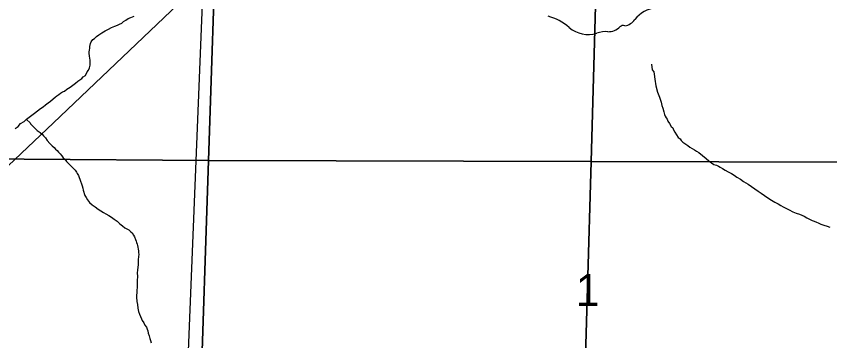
# Model space of a CAD drawing. Extents: x 2010165 to 2382125, y 1060529 to 1407316.
# Drawn here: x 2158400 to 2164031, y 1243143 to 1245392 of the extents above; entities that cross this region are included whole.
import ezdxf

# ---------------------------------------------------------------- set-up
doc = ezdxf.new("R2010")
doc.units = 0
for name, color, linetype in [('GM_X_City_Street', 7, 'Continuous'), ('GM_X_Minor_River', 7, 'Continuous'), ('GM_X_Rail_Line', 7, 'Continuous'), ('GM_X_Section', 7, 'Continuous'), ('GM_X_Section_Text', 7, 'Continuous'), ('GM_X_State_Shield', 7, 'Continuous')]:
    doc.layers.add(name, color=color, linetype=linetype)

msp = doc.modelspace()

# ---------------------------------------------------------------- linework, layer by layer
at = {"layer": 'GM_X_City_Street'}
msp.add_lwpolyline([(2159318.5, 1235161.2), (2159514.5, 1240755.7), (2159578.1, 1242229.6), (2159584.2, 1242899.4), (2159715.4, 1246110.5)], dxfattribs=at)
at = {"layer": 'GM_X_Minor_River'}
for points in [[(2158954.7, 1245251.2), (2158972.5, 1245263.5), (2158992.3, 1245278), (2159016.2, 1245290.5), (2159038, 1245302.9), (2159059.9, 1245313.4), (2159081.8, 1245323.8), (2159099.7, 1245330.2), (2159113.6, 1245336.5), (2159129.5, 1245344.8), (2159141.4, 1245355.1), (2159157.2, 1245365.4), (2159175.1, 1245375.8), (2159193, 1245384.1), (2159205, 1245388.4), (2159214.9, 1245392.6)], [(2158392.6, 1244614.3), (2158412.4, 1244628.7), (2158430, 1244649.1), (2158453.9, 1244663.6), (2158471.6, 1244678), (2158489.4, 1244692.4), (2158507.2, 1244706.8), (2158527, 1244721.2), (2158546.8, 1244737.6), (2158568.6, 1244752.1), (2158586.4, 1244764.5), (2158602.2, 1244778.8), (2158620.1, 1244791.2), (2158635.9, 1244803.6), (2158655.6, 1244820), (2158669.5, 1244830.3), (2158681.3, 1244840.5), (2158695.2, 1244850.8), (2158707.1, 1244859.1), (2158721, 1244867.4), (2158732.9, 1244873.6), (2158750.7, 1244886), (2158760.6, 1244894.2), (2158772.5, 1244900.5), (2158790.3, 1244914.9), (2158800.3, 1244921.1), (2158810.1, 1244929.3), (2158826, 1244941.6), (2158839.8, 1244951.9), (2158853.7, 1244960.2), (2158863.5, 1244972.5), (2158879.4, 1244980.8), (2158891, 1245007.1), (2158898.8, 1245019.3), (2158906.5, 1245033.5), (2158912.2, 1245053.7), (2158912, 1245065.7), (2158911.7, 1245077.8), (2158911.5, 1245087.8), (2158909.3, 1245101.8), (2158907, 1245115.8), (2158904.6, 1245135.8), (2158904.4, 1245145.8), (2158906.3, 1245155.9), (2158908, 1245170), (2158909.8, 1245182.1), (2158913.4, 1245204.2), (2158917.2, 1245214.3), (2158929, 1245230.6), (2158940.9, 1245238.9), (2158954.7, 1245251.2)], [(2162797.2, 1245059.7), (2162801.9, 1245021.6), (2162812.2, 1245007.8), (2162816.5, 1244991.8), (2162821.2, 1244955.8), (2162828.1, 1244909.8), (2162838.9, 1244865.8), (2162851.6, 1244831.9), (2162864.3, 1244796.1), (2162868.7, 1244774.1), (2162875.1, 1244756.1), (2162881.6, 1244730.2), (2162887.9, 1244712.2), (2162892.1, 1244700.3), (2162898.4, 1244688.3), (2162904.6, 1244678.4), (2162910.9, 1244664.5), (2162921.2, 1244648.6), (2162933.6, 1244628.8), (2162943.8, 1244619), (2162950.1, 1244605), (2162958.4, 1244589.1), (2162970.8, 1244569.3), (2162981.2, 1244551.4), (2162995.4, 1244541.7), (2163001.6, 1244531.8), (2163013.9, 1244520), (2163028.1, 1244510.2), (2163048.4, 1244496.5), (2163062.7, 1244484.8), (2163078.9, 1244475.1), (2163095.1, 1244467.3), (2163109.4, 1244457.6), (2163123.6, 1244447.8), (2163174.5, 1244406.6), (2163192.9, 1244390.9), (2163213.2, 1244377.3), (2163229.5, 1244365.6), (2163247.6, 1244359.9), (2163259.8, 1244354.1), (2163272, 1244346.3), (2163288.2, 1244336.6), (2163306.5, 1244324.9), (2163328.8, 1244313.2), (2163351.1, 1244301.6), (2163369.3, 1244289.9), (2163387.7, 1244276.2), (2163412, 1244262.7), (2163434.3, 1244247), (2163466.8, 1244227.6), (2163489.2, 1244212), (2163511.6, 1244196.3), (2163535.9, 1244180.8), (2163556.3, 1244165.1), (2163578.6, 1244149.5), (2163603, 1244133.9), (2163627.4, 1244118.3), (2163651.7, 1244104.7), (2163674, 1244091.1), (2163692.3, 1244081.4), (2163708.5, 1244071.7), (2163730.8, 1244060), (2163751.1, 1244050.4), (2163775.4, 1244036.8), (2163797.6, 1244027.2), (2163821.9, 1244019.6), (2163838, 1244013.9), (2163854.2, 1244006.2), (2163872.5, 1243994.5), (2163890.7, 1243984.8), (2163908.9, 1243977.1), (2163923.1, 1243971.4), (2163939.3, 1243965.7), (2163951.4, 1243959.9), (2163969.6, 1243952.2), (2163989.8, 1243944.6), (2164012, 1243937), (2164032.2, 1243929.3)], [(2158470.6, 1244677.1), (2158496.2, 1244654.4), (2158498.3, 1244646.4), (2158520.8, 1244622.7), (2158545.3, 1244601.1), (2158565.7, 1244585.5), (2158579.9, 1244575.7), (2158588.1, 1244563.8), (2158602.4, 1244550.1), (2158614.9, 1244530.2), (2158633.3, 1244510.5), (2158647.6, 1244494.7), (2158661.9, 1244483), (2158672.1, 1244471.1), (2158682.4, 1244461.3), (2158692.6, 1244449.4), (2158704.9, 1244437.6), (2158715.2, 1244423.8), (2158725.4, 1244411.9), (2158737.7, 1244400.1), (2158748, 1244386.3), (2158758.2, 1244374.4), (2158774.6, 1244356.7), (2158791, 1244340.9), (2158807.3, 1244325.2), (2158817.6, 1244311.3), (2158821.8, 1244301.4), (2158830, 1244289.5), (2158836.3, 1244275.6), (2158840.6, 1244263.6), (2158844.8, 1244249.6), (2158851.2, 1244231.7), (2158855.4, 1244217.7), (2158859.8, 1244201.8), (2158864, 1244187.8), (2158874.8, 1244149.9), (2158883.1, 1244136), (2158893.4, 1244120.1), (2158907.8, 1244102.3), (2158926.1, 1244084.6), (2158946.5, 1244071), (2158966.8, 1244055.3), (2158985.1, 1244043.6), (2159003.4, 1244031.9), (2159019.6, 1244022.2), (2159039.9, 1244010.5), (2159058.2, 1243998.8), (2159076.5, 1243985.1), (2159098.8, 1243971.5), (2159117.2, 1243953.8), (2159135.5, 1243940.1), (2159151.8, 1243926.4), (2159166, 1243918.6), (2159178.2, 1243910.8), (2159192.5, 1243899.1), (2159202.7, 1243891.2), (2159211, 1243875.3), (2159217.2, 1243863.4), (2159225.6, 1243845.5), (2159229.8, 1243833.6), (2159232, 1243823.6), (2159236.2, 1243813.6), (2159238.4, 1243803.6), (2159240.6, 1243791.6), (2159242.9, 1243777.6), (2159245.1, 1243765.6), (2159245.3, 1243753.6), (2159247.5, 1243743.6), (2159245.9, 1243725.5), (2159244.2, 1243705.4), (2159242.6, 1243687.3), (2159242.9, 1243669.2), (2159241.2, 1243653.1), (2159239.5, 1243633.1), (2159237.9, 1243613), (2159238.4, 1243588.9), (2159236.9, 1243560.8), (2159237.5, 1243526.6), (2159234.4, 1243480.4), (2159232.8, 1243454.3), (2159231, 1243444.2), (2159233.6, 1243414.2), (2159238, 1243394.2), (2159242.4, 1243368.2), (2159246.9, 1243346.2), (2159253.2, 1243328.3), (2159259.6, 1243310.3), (2159265.9, 1243294.4), (2159272.1, 1243284.5), (2159282.4, 1243268.6), (2159290.8, 1243250.7), (2159301.1, 1243236.9), (2159305.3, 1243222.9), (2159309.6, 1243210.9), (2159313.9, 1243197), (2159320.2, 1243177), (2159324.6, 1243159.1), (2159328.9, 1243145.1), (2159333.2, 1243129.1)]]:
    msp.add_lwpolyline(points, dxfattribs=at)
at = {"layer": 'GM_X_Rail_Line'}
msp.add_lwpolyline([(2148913.3, 1235390.1), (2151121.4, 1237488.2), (2153352.2, 1239614.8), (2153929.8, 1240167.4), (2154543.4, 1240751.8), (2155500, 1241661.6), (2155854.6, 1241999.2), (2157533.9, 1243588.4), (2158657.3, 1244653.5), (2159470.9, 1245426.4), (2160143.4, 1246061.6), (2160845.1, 1246725.4), (2160959.7, 1246827.7)], dxfattribs=at)
at = {"layer": 'GM_X_Section'}
for points in [[(2157328.9, 1246108.9), (2159787.4, 1246122.3), (2159729.9, 1244392.5), (2157175.7, 1244411.7), (2157281.9, 1246108.8)], [(2159787.4, 1246122.3), (2162427.3, 1246126.4), (2162378.4, 1244386), (2159729.9, 1244392.5)], [(2163024.8, 1246131), (2165055.4, 1246148.6), (2165056, 1245624.9), (2165040.8, 1244939.9), (2165028.5, 1244379.4), (2162378.4, 1244386), (2162427.3, 1246126.4)], [(2157175.7, 1244411.7), (2159729.9, 1244392.5), (2159672.2, 1242656.1), (2157067.8, 1242687.8)], [(2159729.9, 1244392.5), (2162378.4, 1244386), (2162329.4, 1242638.6), (2159672.2, 1242656.1)], [(2162378.4, 1244386), (2165028.5, 1244379.4), (2165025.9, 1244267.5), (2165011.3, 1243537.5), (2165002.8, 1242817.7), (2165000.8, 1242627.9), (2162329.4, 1242638.6)]]:
    msp.add_lwpolyline(points, close=True, dxfattribs=at)
at = {"layer": 'GM_X_State_Shield'}
for centre, radius, start, end in [((2162842.7, 1245246.7), 202.2, 94.4031, 142.5768), ((2161999.5, 1245068.6), 333.6, 47.1842, 75.836), ((2162498, 1245398), 112.8, 268.777, 315.5493), ((2162600, 1245295.7), 31.8, 65.7517, 132.6484), ((2162586.5, 1245440.9), 119.3, 282.8732, 323.2771), ((2162360.3, 1245477.1), 211.7, 230.7004, 286.2918), ((2162482.6, 1245111.8), 173.9, 85.6951, 111.2099)]:
    msp.add_arc(centre, radius, start, end, dxfattribs=at)

# ---------------------------------------------------------------- texts
at = {"layer": 'GM_X_Section_Text'}
msp.add_text('1', height=221, rotation=0, dxfattribs=at).set_placement((2162273.1, 1243384.3))

doc.saveas('drawing.dxf')
